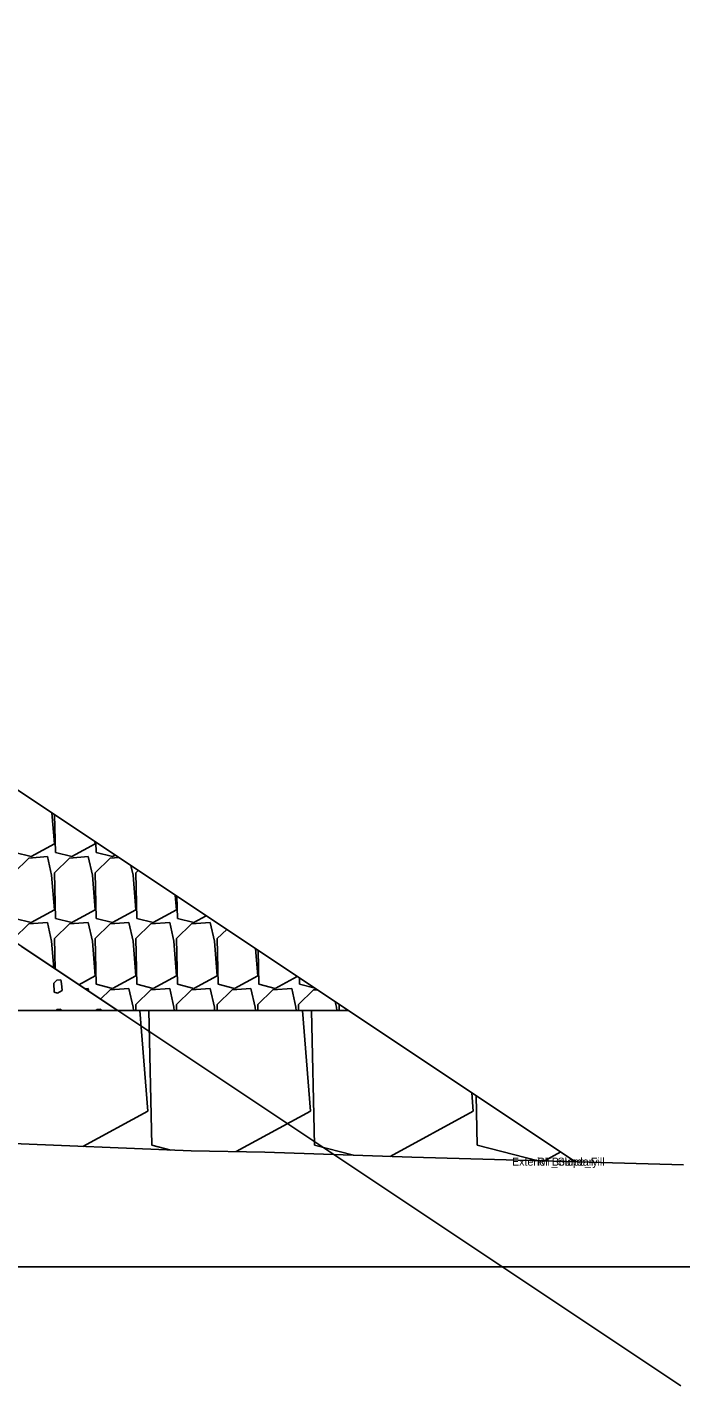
# Model space of a CAD drawing. Extents: x -26 to 2903, y -10 to 63.
# Drawn here: x 1487.03 to 1497.23, y -1.86 to 19.36 of the extents above; entities that cross this region are included whole.
import ezdxf

# ---------------------------------------------------------------- set-up
doc = ezdxf.new("R2010")
doc.units = 0
for name, color, linetype in [('Default', 7, 'Continuous'), ('Exist Cross Section Cell', 7, 'Continuous'), ('Exist XS Ground Line', 7, 'Continuous'), ('Prop XS SE Text', 7, 'Continuous'), ('Scratch_Level_0', 7, 'Continuous')]:
    doc.layers.add(name, color=color, linetype=linetype)

msp = doc.modelspace()

# ---------------------------------------------------------------- linework, layer by layer
at = {"layer": 'Default'}
msp.add_line((1465.403, 19.359), (1497.228, -1.86), dxfattribs=at)
at = {"layer": 'Exist Cross Section Cell'}
msp.add_line((1450, 0), (1600, 0), dxfattribs=at)
at = {"layer": 'Exist XS Ground Line'}
for p, q in [((1485.432, 1.98), (1489.586, 1.809)), ((1489.586, 1.809), (1490.737, 1.791)), ((1490.737, 1.791), (1493.031, 1.712)), ((1493.031, 1.712), (1497.27, 1.593))]:
    msp.add_line(p, q, dxfattribs=at)
at = {"layer": 'Prop XS SE Text'}
for p, q in [((1469.5, 19.031), (1495.585, 1.64)), ((1487.452, 6.603), (1487.414, 7.087)), ((1487.455, 7.06), (1487.467, 6.47)), ((1487.088, 6.405), (1487.452, 6.603)), ((1487.723, 6.405), (1488.087, 6.603)), ((1488.087, 6.603), (1488.084, 6.641)), ((1488.099, 6.631), (1488.102, 6.47)), ((1487.053, 6.382), (1486.817, 6.154)), ((1486.832, 6.47), (1487.088, 6.405)), ((1487.346, 6.405), (1487.053, 6.382)), ((1487.409, 6.116), (1487.346, 6.405)), ((1487.688, 6.382), (1487.452, 6.154)), ((1487.467, 6.47), (1487.723, 6.405)), ((1487.981, 6.405), (1487.688, 6.382)), ((1488.044, 6.116), (1487.981, 6.405)), ((1488.323, 6.382), (1488.087, 6.154)), ((1488.102, 6.47), (1488.358, 6.405)), ((1488.456, 6.393), (1488.323, 6.382)), ((1488.358, 6.405), (1488.401, 6.429)), ((1487.452, 6.154), (1487.467, 5.44)), ((1488.087, 6.154), (1488.102, 5.44)), ((1488.679, 6.116), (1488.646, 6.266)), ((1488.759, 6.19), (1488.722, 6.154)), ((1488.722, 6.154), (1488.737, 5.44)), ((1487.452, 5.573), (1487.409, 6.116)), ((1488.087, 5.573), (1488.044, 6.116)), ((1488.722, 5.573), (1488.679, 6.116)), ((1489.357, 5.573), (1489.339, 5.804)), ((1489.365, 5.787), (1489.372, 5.44)), ((1487.088, 5.376), (1487.452, 5.573)), ((1487.723, 5.376), (1488.087, 5.573)), ((1488.358, 5.376), (1488.722, 5.573)), ((1488.993, 5.376), (1489.357, 5.573)), ((1487.053, 5.353), (1486.817, 5.124)), ((1486.832, 5.44), (1487.088, 5.376)), ((1487.346, 5.376), (1487.053, 5.353)), ((1487.409, 5.086), (1487.346, 5.376)), ((1487.688, 5.353), (1487.452, 5.124)), ((1487.467, 5.44), (1487.723, 5.376)), ((1487.981, 5.376), (1487.688, 5.353)), ((1488.044, 5.086), (1487.981, 5.376)), ((1488.323, 5.353), (1488.087, 5.124)), ((1488.102, 5.44), (1488.358, 5.376)), ((1488.616, 5.376), (1488.323, 5.353)), ((1488.679, 5.086), (1488.616, 5.376)), ((1488.958, 5.353), (1488.722, 5.124)), ((1488.737, 5.44), (1488.993, 5.376)), ((1489.251, 5.376), (1488.958, 5.353)), ((1489.314, 5.086), (1489.251, 5.376)), ((1489.593, 5.353), (1489.357, 5.124)), ((1489.372, 5.44), (1489.628, 5.376)), ((1489.885, 5.376), (1489.593, 5.353)), ((1489.628, 5.376), (1489.822, 5.481)), ((1489.949, 5.086), (1489.885, 5.376)), ((1487.452, 5.124), (1487.462, 4.651)), ((1488.087, 5.124), (1488.102, 4.411)), ((1488.722, 5.124), (1488.737, 4.411)), ((1489.357, 5.124), (1489.372, 4.411)), ((1490.141, 5.269), (1489.992, 5.124)), ((1489.992, 5.124), (1490.007, 4.411)), ((1486.936, 5), (1488.436, 4)), ((1487.442, 4.664), (1487.409, 5.086)), ((1488.087, 4.544), (1488.044, 5.086)), ((1488.722, 4.544), (1488.679, 5.086)), ((1489.357, 4.544), (1489.314, 5.086)), ((1489.992, 4.544), (1489.949, 5.086)), ((1490.627, 4.544), (1490.593, 4.968)), ((1490.63, 4.943), (1490.642, 4.411)), ((1487.492, 4.474), (1487.445, 4.429)), ((1487.551, 4.479), (1487.492, 4.474)), ((1487.563, 4.421), (1487.551, 4.479)), ((1487.832, 4.405), (1488.087, 4.544)), ((1488.358, 4.346), (1488.722, 4.544)), ((1488.993, 4.346), (1489.357, 4.544)), ((1489.628, 4.346), (1489.992, 4.544)), ((1490.263, 4.346), (1490.627, 4.544)), ((1490.898, 4.346), (1491.243, 4.534)), ((1491.275, 4.513), (1491.277, 4.411)), ((1487.445, 4.429), (1487.448, 4.286)), ((1487.448, 4.286), (1487.499, 4.273)), ((1487.499, 4.273), (1487.572, 4.313)), ((1487.572, 4.313), (1487.563, 4.421)), ((1487.981, 4.346), (1487.926, 4.342)), ((1487.991, 4.299), (1487.981, 4.346)), ((1488.102, 4.411), (1488.358, 4.346)), ((1488.323, 4.323), (1488.173, 4.178)), ((1488.616, 4.346), (1488.323, 4.323)), ((1488.679, 4.056), (1488.616, 4.346)), ((1488.958, 4.323), (1488.722, 4.094)), ((1488.737, 4.411), (1488.993, 4.346)), ((1489.251, 4.346), (1488.958, 4.323)), ((1489.314, 4.056), (1489.251, 4.346)), ((1489.593, 4.323), (1489.357, 4.094)), ((1489.372, 4.411), (1489.628, 4.346)), ((1489.885, 4.346), (1489.593, 4.323)), ((1489.949, 4.056), (1489.885, 4.346)), ((1490.228, 4.323), (1489.992, 4.094)), ((1490.007, 4.411), (1490.263, 4.346)), ((1490.52, 4.346), (1490.228, 4.323)), ((1490.584, 4.056), (1490.52, 4.346)), ((1490.863, 4.323), (1490.627, 4.094)), ((1490.642, 4.411), (1490.898, 4.346)), ((1491.155, 4.346), (1490.863, 4.323)), ((1491.219, 4.056), (1491.155, 4.346)), ((1491.497, 4.323), (1491.262, 4.094)), ((1491.277, 4.411), (1491.521, 4.349)), ((1491.553, 4.327), (1491.497, 4.323)), ((1488.684, 4), (1488.679, 4.056)), ((1488.722, 4.094), (1488.724, 4)), ((1489.319, 4), (1489.314, 4.056)), ((1489.357, 4.094), (1489.359, 4)), ((1489.953, 4), (1489.949, 4.056)), ((1489.992, 4.094), (1489.994, 4)), ((1490.588, 4), (1490.584, 4.056)), ((1490.627, 4.094), (1490.629, 4)), ((1491.223, 4), (1491.219, 4.056)), ((1491.262, 4.094), (1491.264, 4)), ((1491.854, 4.056), (1491.836, 4.139)), ((1491.858, 4), (1491.854, 4.056)), ((1491.899, 4.097), (1491.896, 4.094)), ((1491.896, 4.094), (1491.898, 4)), ((1492.044, 4), (1477.373, 4)), ((1487.492, 4.018), (1487.473, 4)), ((1487.551, 4.023), (1487.492, 4.018)), ((1487.556, 4), (1487.551, 4.023)), ((1488.119, 4.018), (1488.1, 4)), ((1488.178, 4.023), (1488.119, 4.018)), ((1488.183, 4), (1488.178, 4.023)), ((1488.91, 2.43), (1488.787, 4)), ((1488.926, 4), (1488.972, 1.897)), ((1491.45, 2.43), (1491.326, 4)), ((1491.466, 4), (1491.511, 1.897)), ((1493.99, 2.43), (1493.967, 2.718)), ((1494.034, 2.673), (1494.051, 1.897)), ((1487.896, 1.878), (1488.91, 2.43)), ((1490.287, 1.798), (1491.45, 2.43)), ((1492.691, 1.724), (1493.99, 2.43)), ((1488.972, 1.897), (1489.269, 1.822)), ((1491.511, 1.897), (1492.12, 1.743)), ((1494.051, 1.897), (1495.004, 1.656)), ((1495.102, 1.654), (1495.356, 1.792))]:
    msp.add_line(p, q, dxfattribs=at)

# ---------------------------------------------------------------- texts
at = {"layer": 'Scratch_Level_0'}
for s, p in [('Exterior Boundary', (1494.593, 1.578)), ('RT_Slope_Fill', (1494.989, 1.578)), ('RT_Slope_Fill', (1494.989, 1.578))]:
    msp.add_text(s, height=0.125, dxfattribs=at).set_placement(p)

doc.saveas('drawing.dxf')
